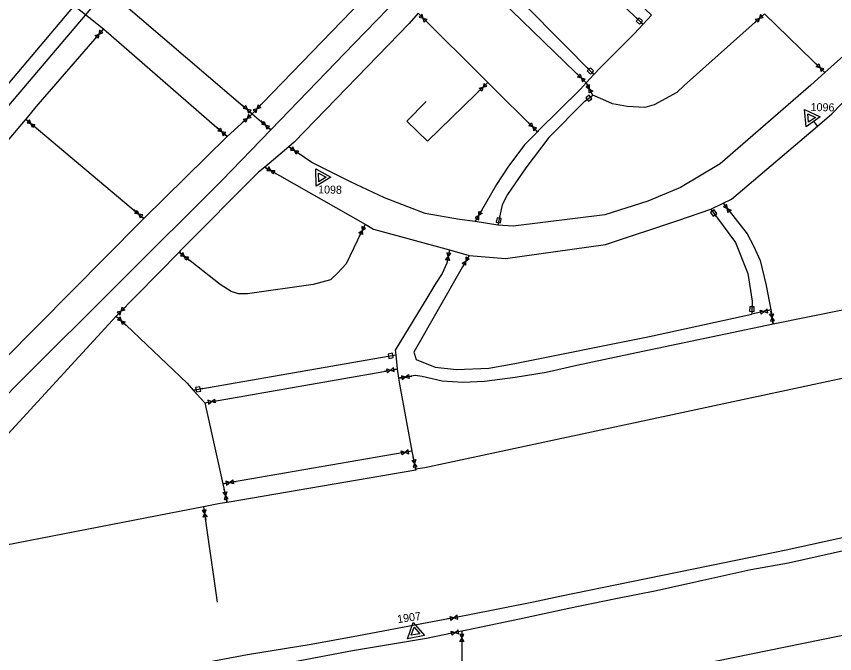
# Model space of a CAD drawing. Extents: x 349903 to 372392, y 368574 to 383062.
# Drawn here: x 364034 to 364545, y 373000 to 373398 of the extents above; entities that cross this region are included whole.
import ezdxf

# ---------------------------------------------------------------- set-up
doc = ezdxf.new("R2010")
doc.units = 0
for name, color, linetype in [('Niveau 1', 7, 'Continuous'), ('Niveau 10', 7, 'Continuous'), ('Niveau 2', 7, 'Continuous'), ('Niveau 3', 7, 'Continuous')]:
    doc.layers.add(name, color=color, linetype=linetype)

msp = doc.modelspace()

# ---------------------------------------------------------------- linework, layer by layer
at = {"layer": 'Niveau 1'}
for p, q in [((364289.667, 373395.829), (364291.017, 373394.491)), ((364496.537, 373395.811), (364495.128, 373394.535)), ((364088.295, 373390.713), (364086.932, 373389.11)), ((364084.096, 373385.772), (364082.865, 373384.323)), ((364534.581, 373367.935), (364533.221, 373369.264)), ((364539.218, 373363.403), (364537.713, 373364.874)), ((364385.435, 373361.514), (364384.074, 373362.841)), ((364390.076, 373356.986), (364388.57, 373358.456)), ((364328.606, 373357.213), (364327.099, 373355.744)), ((364390.076, 373356.986), (364391.049, 373355.12)), ((364323.964, 373352.686), (364322.602, 373351.359)), ((364393.076, 373351.238), (364393.956, 373349.553)), ((364176.457, 373341.864), (364175.022, 373343.111)), ((364185.872, 373342.257), (364187.197, 373343.619)), ((364181.35, 373337.609), (364179.762, 373338.99)), ((364181.35, 373337.609), (364182.818, 373339.117)), ((364039.803, 373334.226), (364041.414, 373332.872)), ((364176.528, 373333.273), (364175.115, 373332.002)), ((364181.35, 373337.609), (364179.785, 373336.202)), ((364188.062, 373331.899), (364186.626, 373333.144)), ((364044.766, 373330.054), (364046.222, 373328.83)), ((364160.727, 373327.798), (364159.3, 373329.055)), ((364192.961, 373327.651), (364191.371, 373329.03)), ((364355.018, 373331.016), (364353.668, 373332.354)), ((364359.624, 373326.452), (364358.13, 373327.933)), ((364165.592, 373323.512), (364164.013, 373324.903)), ((364204.197, 373317.088), (364205.928, 373315.892)), ((364209.532, 373313.403), (364211.096, 373312.322)), ((364189.144, 373304.348), (364190.972, 373303.305)), ((364194.777, 373301.136), (364196.428, 373300.195)), ((364475.621, 373281.87), (364476.907, 373280.205)), ((364108.711, 373276.334), (364107.258, 373277.56)), ((364323.967, 373275.88), (364324.928, 373277.521)), ((364479.585, 373276.739), (364480.748, 373275.234)), ((364113.667, 373272.153), (364112.059, 373273.51)), ((364320.689, 373270.286), (364321.753, 373272.101)), ((364251.918, 373268.632), (364250.995, 373266.741)), ((364249.076, 373262.804), (364248.242, 373261.096)), ((364135.58, 373251.205), (364137.229, 373249.898)), ((364304.607, 373252.578), (364304.194, 373250.515)), ((364140.662, 373247.179), (364142.153, 373245.998)), ((364303.335, 373246.22), (364302.962, 373244.356)), ((364316.87, 373249.202), (364315.806, 373247.386)), ((364313.592, 373243.607), (364312.631, 373241.967)), ((364100.909, 373215.889), (364102.24, 373217.246)), ((364096.37, 373211.258), (364097.844, 373212.761)), ((364096.37, 373211.258), (364097.902, 373209.815)), ((364499.034, 373213.671), (364497.178, 373213.261)), ((364505.366, 373215.068), (364503.311, 373214.615)), ((364505.789, 373212.546), (364505.502, 373214.426)), ((364101.091, 373206.813), (364102.475, 373205.51)), ((364506.764, 373206.136), (364506.448, 373208.216)), ((364265.558, 373177.067), (364263.686, 373176.736)), ((364271.943, 373178.196), (364269.871, 373177.83)), ((364272.778, 373172.441), (364274.856, 373172.775)), ((364279.18, 373173.471), (364281.057, 373173.773)), ((364151.663, 373157.064), (364153.735, 373157.43)), ((364158.048, 373158.192), (364159.92, 373158.523)), ((364274.71, 373125.754), (364272.837, 373125.424)), ((364281.095, 373126.881), (364279.023, 373126.516)), ((364282.231, 373121.369), (364281.834, 373123.229)), ((364283.584, 373115.028), (364283.145, 373117.086)), ((364169.412, 373107.669), (364171.286, 373107.994)), ((364163.024, 373106.559), (364165.097, 373106.919)), ((364164.187, 373101.213), (364163.783, 373103.07)), ((364165.567, 373094.877), (364165.12, 373096.933)), ((364150.943, 373092.135), (364151.269, 373090.056)), ((364151.95, 373085.73), (364152.245, 373083.851)), ((364305.231, 373022.411), (364303.363, 373022.059)), ((364311.603, 373023.61), (364309.535, 373023.221)), ((364305.929, 373013.091), (364304.066, 373012.711)), ((364312.283, 373014.384), (364310.221, 373013.965)), ((364312.283, 373014.384), (364312.282, 373012.28)), ((364312.282, 373007.9), (364312.281, 373005.998))]:
    msp.add_line(p, q, dxfattribs=at)
for points in [[(364290.557, 373396.733), (364288.786, 373394.935), (364287.46, 373399.804), (364285.677, 373398.018)], [(364497.391, 373394.874), (364495.692, 373396.739), (364500.625, 373397.801), (364498.937, 373399.677)], [(364085.065, 373384.954), (364083.137, 373386.582), (364087.89, 373388.278), (364085.972, 373389.918)], [(364533.697, 373367.025), (364535.455, 373368.835), (364536.817, 373363.977), (364538.586, 373365.776)], [(364384.552, 373360.603), (364386.308, 373362.415), (364387.674, 373357.557), (364389.442, 373359.358)], [(364324.852, 373351.781), (364323.085, 373353.582), (364327.975, 373354.826), (364326.219, 373356.639)], [(364394.199, 373351.829), (364391.966, 373350.654), (364392.181, 373355.695), (364389.94, 373354.535)], [(364184.96, 373343.138), (364186.773, 373341.384), (364181.918, 373340.012), (364183.722, 373338.246)], [(364175.628, 373340.904), (364177.278, 373342.813), (364178.919, 373338.042), (364180.581, 373339.941)], [(364045.579, 373331.027), (364043.962, 373329.09), (364042.24, 373333.834), (364040.61, 373331.907)], [(364177.38, 373332.333), (364175.687, 373334.204), (364180.623, 373335.249), (364178.941, 373337.131)], [(364187.235, 373330.938), (364188.882, 373332.85), (364190.53, 373328.081), (364192.189, 373329.982)], [(364159.892, 373326.844), (364161.554, 373328.743), (364163.164, 373323.961), (364164.839, 373325.849)], [(364354.129, 373330.112), (364355.899, 373331.91), (364357.227, 373327.042), (364359.009, 373328.829)], [(364210.249, 373314.449), (364208.822, 373312.368), (364206.661, 373316.927), (364205.22, 373314.856)], [(364195.401, 373302.24), (364194.158, 373300.044), (364191.612, 373304.4), (364190.355, 373302.212)], [(364107.897, 373275.363), (364109.518, 373277.296), (364111.23, 373272.55), (364112.864, 373274.473)], [(364322.871, 373276.518), (364325.052, 373275.249), (364320.666, 373272.755), (364322.839, 373271.472)], [(364480.586, 373277.517), (364478.594, 373275.969), (364477.92, 373280.969), (364475.918, 373279.433)], [(364250.217, 373262.252), (364247.946, 373263.351), (364252.129, 373266.172), (364249.865, 373267.285)], [(364141.447, 373248.175), (364139.886, 373246.192), (364138.028, 373250.884), (364136.454, 373248.911)], [(364304.579, 373245.975), (364302.103, 373246.463), (364305.435, 373250.252), (364302.962, 373250.755)], [(364314.689, 373242.97), (364312.507, 373244.239), (364316.893, 373246.733), (364314.72, 373248.016)], [(364100.001, 373216.773), (364101.808, 373215.012), (364096.947, 373213.659), (364098.744, 373211.886)], [(364499.311, 373212.434), (364498.76, 373214.896), (364503.571, 373213.373), (364503.035, 373215.839)], [(364101.957, 373207.739), (364100.233, 373205.897), (364098.782, 373210.729), (364097.046, 373208.897)], [(364504.536, 373212.351), (364507.029, 373212.739), (364505.192, 373208.039), (364507.688, 373208.411)], [(364265.783, 373175.819), (364265.336, 373178.302), (364270.078, 373176.578), (364269.646, 373179.065)], [(364278.974, 373174.722), (364279.383, 373172.232), (364274.668, 373174.029), (364275.061, 373171.537)], [(364157.823, 373159.44), (364158.27, 373156.957), (364153.528, 373158.681), (364153.959, 373156.195)], [(364274.934, 373124.506), (364274.488, 373126.99), (364279.229, 373125.264), (364278.799, 373127.751)], [(364280.992, 373121.101), (364283.458, 373121.635), (364281.902, 373116.835), (364284.372, 373117.354)], [(364169.191, 373108.917), (364169.631, 373106.433), (364164.894, 373108.171), (364165.318, 373105.683)], [(364162.949, 373100.939), (364165.413, 373101.483), (364163.877, 373096.677), (364166.345, 373097.206)], [(364153.202, 373085.931), (364150.71, 373085.531), (364152.525, 373090.239), (364150.03, 373089.855)], [(364305.469, 373021.166), (364304.995, 373023.644), (364309.755, 373021.973), (364309.297, 373024.453)], [(364306.186, 373011.849), (364305.675, 373014.32), (364310.46, 373012.719), (364309.965, 373015.193)], [(364313.549, 373007.904), (364311.027, 373007.897), (364313.55, 373012.265), (364311.027, 373012.274)]]:
    msp.add_lwpolyline(points, close=True, dxfattribs=at)
at = {"layer": 'Niveau 10'}
for p, q in [((364285.063, 373400.395), (364328.606, 373357.213)), ((364328.606, 373357.213), (364359.624, 373326.452)), ((364389.196, 373345.562), (364394.114, 373349.244)), ((364039.803, 373334.226), (364113.667, 373272.153)), ((364534.488, 373329.942), (364532.311, 373332.92)), ((364304.607, 373252.578), (364316.87, 373249.202)), ((364144.476, 373164.983), (364270.978, 373186.965)), ((364151.663, 373157.064), (364271.943, 373178.196)), ((364281.095, 373126.881), (364163.024, 373106.559)), ((364150.943, 373092.135), (364159.486, 373032.506)), ((364312.283, 373014.384), (364312.283, 372962.676))]:
    msp.add_line(p, q, dxfattribs=at)
for points in [[(366766.936, 376040.549), (366763.46, 376037.341), (366667.812, 375934.705), (366617.063, 375879.047), (366370.17, 375608.973), (366271.904, 375503.403), (366107.898, 375322.357), (365954.331, 375156.168), (365788.236, 374978.178), (365607.938, 374785.446), (365518.975, 374699.397), (365364.307, 374546.897), (365333.229, 374555.57), (364778.418, 374088.297), (364472.26, 373830.629), (364367.399, 373726.809), (364168.973, 373500.723), (364094.413, 373420.15), (363966.939, 373269.827), (363827.246, 373103.73), (363758.548, 373021.97), (363751.696, 373026.803)], [(364538.715, 373680.887), (364536.151, 373678.533), (364358.178, 373498.065), (364245.01, 373381.635), (364192.961, 373327.651)], [(364656.397, 373468.407), (364643.883, 373457.218), (364539.218, 373363.403)], [(364430.802, 373399.243), (364377.539, 373450.039), (364336.582, 373408.713), (364390.076, 373356.986)], [(364425.521, 373393.521), (364380.18, 373436.016), (364373.725, 373435.313), (364351.977, 373413.791), (364352.959, 373404.508), (364394.889, 373362.215)], [(364083.659, 373421.39), (364181.35, 373337.609)], [(364262.489, 373421.809), (364255.966, 373415.038), (364181.35, 373337.609)], [(364070.087, 373405.377), (364028.51, 373356.119), (364028.071, 373355.613)], [(364070.087, 373405.377), (364088.295, 373390.713)], [(364285.063, 373400.395), (364279.438, 373394.126), (364207.614, 373319.98), (364204.197, 373317.088)], [(364501.344, 373400.163), (364451.213, 373355.282), (364446.635, 373350.934), (364432.421, 373343.206), (364426.639, 373341.515), (364415.556, 373342.24), (364406.401, 373343.93), (364400.378, 373346.587), (364394.114, 373349.244)], [(364430.802, 373399.243), (364425.521, 373393.521)], [(364501.344, 373400.163), (364539.218, 373363.403)], [(364088.295, 373390.713), (364046.158, 373341.965), (364039.803, 373334.226)], [(364088.295, 373390.713), (364165.592, 373323.512)], [(364425.521, 373393.521), (364419.967, 373387.505), (364398.863, 373366.53), (364394.889, 373362.215)], [(364539.218, 373363.403), (364530.306, 373355.415), (364473.73, 373306.466), (364448.977, 373291.569), (364428.468, 373283.056), (364401.595, 373274.543), (364344.311, 373267.449), (364334.745, 373267.991)], [(364394.889, 373362.215), (364390.076, 373356.986)], [(364328.606, 373357.213), (364290.935, 373320.539), (364277.922, 373333.126), (364290.021, 373345.255)], [(364390.076, 373356.986), (364386.414, 373353.008), (364360.098, 373326.921), (364359.624, 373326.452)], [(364394.114, 373349.244), (364390.076, 373356.986)], [(364534.488, 373329.942), (364543.423, 373337.52), (364555, 373349.444)], [(364389.196, 373345.562), (364366.693, 373322.893), (364352.379, 373303.868), (364340.8, 373287.262), (364337.422, 373280.813), (364334.745, 373267.991)], [(364039.803, 373334.226), (364039.522, 373333.883), (363990.705, 373276.356), (363985.065, 373270.259)], [(364181.35, 373337.609), (364165.592, 373323.512)], [(364181.35, 373337.609), (364192.961, 373327.651)], [(364192.961, 373327.651), (364162.307, 373295.858), (364035.598, 373169.725), (363962.088, 373095.015), (363954.492, 373087.114)], [(364475.621, 373281.87), (364480.719, 373284.337), (364534.488, 373329.942)], [(364165.592, 373323.512), (364113.667, 373272.153)], [(364359.624, 373326.452), (364351.442, 373318.336), (364341.065, 373304.229), (364334.063, 373293.4), (364320.689, 373270.286)], [(364204.197, 373317.088), (364189.144, 373304.348)], [(364320.689, 373270.286), (364310.828, 373271.547), (364289.361, 373275.252), (364263.902, 373285.184), (364242.685, 373295.116), (364218.64, 373307.176), (364204.197, 373317.088)], [(364189.144, 373304.348), (364185.3, 373301.094), (364136.488, 373252.13), (364135.58, 373251.205)], [(364189.144, 373304.348), (364251.918, 373268.632)], [(364467.815, 373278.093), (364475.621, 373281.87)], [(364475.621, 373281.87), (364490.608, 373262.553), (364494.475, 373255.076), (364498.757, 373245.937), (364502.487, 373230.291), (364505.366, 373215.068)], [(364316.87, 373249.202), (364339.582, 373247.262), (364402.013, 373255.976), (364447.256, 373271.044), (364467.815, 373278.093)], [(364467.815, 373278.093), (364483.351, 373257.235), (364491.019, 373237.928), (364493.694, 373220.587), (364493.542, 373212.498)], [(364113.667, 373272.153), (364111.574, 373270.083), (363982.809, 373140.47)], [(364251.918, 373268.632), (364239.952, 373243.824), (364234.882, 373238.254), (364230.295, 373233.896), (364219.432, 373230.99), (364178.392, 373225.178), (364172.84, 373225.178), (364168.253, 373226.631), (364161.252, 373230.99), (364135.58, 373251.205)], [(364251.918, 373268.632), (364257.196, 373265.629), (364304.607, 373252.578)], [(364334.745, 373267.991), (364320.689, 373270.286)], [(364135.58, 373251.205), (364096.37, 373211.258)], [(364304.607, 373252.578), (364302.962, 373244.356), (364300.041, 373237.913), (364296.144, 373231.872), (364290.48, 373222.346), (364270.656, 373189.892), (364270.978, 373186.965)], [(364316.87, 373249.202), (364312.631, 373241.967), (364282.382, 373188.679), (364283.747, 373184.118), (364295.729, 373179.405), (364308.924, 373177.884), (364329.095, 373178.796), (364345.324, 373181.533), (364429.576, 373198.58), (364493.542, 373212.498)], [(364150.943, 373092.135), (364012.353, 373065.204), (364000.914, 373067.39), (363992.232, 373077.181), (363991.147, 373091.33), (364000.483, 373107.002), (364096.37, 373211.258)], [(364096.37, 373211.258), (364102.475, 373205.51), (364140.593, 373169.261), (364144.476, 373164.983)], [(364505.366, 373215.068), (364493.542, 373212.498)], [(364505.366, 373215.068), (364505.525, 373214.229), (364506.764, 373206.136)], [(364550.15, 373214.917), (364506.764, 373206.136)], [(364506.764, 373206.136), (364417.51, 373187.409), (364384.076, 373180.316), (364365.04, 373176.08), (364345.581, 373172.886), (364326.476, 373170.401), (364312.924, 373169.692), (364300.01, 373170.579), (364287.45, 373173.418), (364283.204, 373174.128), (364272.778, 373172.441)], [(364270.978, 373186.965), (364271.943, 373178.196)], [(364586.537, 373180.264), (364583.006, 373179.266), (364289.143, 373116.522), (364283.343, 373115.532)], [(364271.943, 373178.196), (364272.778, 373172.441)], [(364272.778, 373172.441), (364273.312, 373168.763), (364281.095, 373126.881)], [(364144.476, 373164.983), (364151.663, 373157.064)], [(364151.663, 373157.064), (364163.024, 373106.559)], [(364834.323, 373138.871), (364827.813, 373137.421), (364797.778, 373130.299), (364760.83, 373121.331), (364716.908, 373110.965), (364677.508, 373101.894), (364631.326, 373091.528), (364595.801, 373082.781), (364570.934, 373077.274), (364514.963, 373064.964), (364476.532, 373057.189), (364418.401, 373045.203), (364373.51, 373036.132), (364357.135, 373032.569), (364316.12, 373024.47), (364311.603, 373023.61)], [(364281.095, 373126.881), (364283.584, 373115.028)], [(364901.855, 372960.505), (364857.883, 373060.904), (364833.992, 373117.76), (364821.925, 373123.905), (364757.949, 373109.888), (364708.914, 373099.135), (364654.133, 373086.461), (364627.7, 373080.317), (364578.815, 373070.37), (364548.934, 373064.222), (364516.372, 373056.92), (364493.004, 373052.693), (364462.965, 373046.161), (364433.85, 373039.628), (364408.567, 373034.633), (364379.069, 373028.484), (364348.422, 373021.952), (364315.477, 373015.035), (364312.283, 373014.384)], [(364283.584, 373115.028), (364165.567, 373094.877)], [(364163.024, 373106.559), (364165.567, 373094.877)], [(364165.567, 373094.877), (364161.381, 373094.163), (364150.943, 373092.135)], [(364805.653, 372919.098), (364788.998, 372958.027), (364776.773, 372985.995), (364767.055, 373003.28), (364758.277, 373015.221), (364745.425, 373025.277), (364724.735, 373034.391), (364706.866, 373038.791), (364687.117, 373039.733), (364670.502, 373036.276), (364637.273, 373029.363), (364370.465, 372975.051), (364312.283, 372962.676)], [(364311.603, 373023.61), (364290.607, 373019.611), (364247.782, 373011.512), (364218.07, 373006.005), (364178.347, 372999.526), (364139.688, 372992.399), (364116.113, 372987.54), (364096.413, 372982.68), (364063.567, 372971.99), (364050.421, 372966.32), (363965.162, 372925.826), (363930.929, 372908.981), (363888.718, 372891.487), (363852.87, 372883.389), (363787.143, 372871.393)], [(364312.283, 373014.384), (364290.156, 373009.868), (364244.05, 373002.044), (364206.658, 372995.129), (364187.235, 372991.307), (364148.317, 372984.228), (364117.278, 372978.038), (364095.677, 372972.757), (364072.896, 372966.276), (364060.19, 372961.724), (364035.685, 372949.707), (364006.17, 372936.779), (363959.937, 372912.856), (363943.963, 372905.208), (363926.174, 372893.737), (363907.297, 372880.81), (363892.666, 372869.777), (363881.23, 372860.126), (363866.164, 372845.56), (363850.009, 372829.719), (363827.973, 372804.68)]]:
    msp.add_lwpolyline(points, dxfattribs=at)
at = {"layer": 'Niveau 2'}
for points in [[(364536.272, 373335.698), (364527.454, 373329.536), (364526.526, 373340.253)], [(364533.304, 373335.407), (364528.896, 373332.326), (364528.433, 373337.686)], [(364230.521, 373298.112), (364221.365, 373292.463), (364221.051, 373303.216)], [(364227.541, 373297.991), (364222.964, 373295.167), (364222.809, 373300.545)], [(364281.859, 373019.814), (364288.892, 373011.672), (364278.326, 373009.652)], [(364282.453, 373016.891), (364285.968, 373012.821), (364280.684, 373011.813)]]:
    msp.add_lwpolyline(points, close=True, dxfattribs=at)
at = {"layer": 'Niveau 3'}
for p, q in [((364421.028, 373397.712), (364422.216, 373396.604)), ((364424.247, 373394.709), (364425.521, 373393.521)), ((364390.562, 373366.577), (364391.706, 373365.424)), ((364393.662, 373363.452), (364394.889, 373362.215)), ((364392.72, 373348.199), (364394.114, 373349.244)), ((364389.196, 373345.562), (364390.496, 373346.535)), ((364468.86, 373276.699), (364467.815, 373278.093)), ((364336.012, 373274.003), (364335.678, 373272.413)), ((364471.501, 373273.177), (364470.526, 373274.477)), ((364335.104, 373269.696), (364334.745, 373267.991)), ((364493.649, 373218.641), (364493.621, 373217.017)), ((364493.572, 373214.24), (364493.542, 373212.498)), ((364264.922, 373185.932), (364266.523, 373186.205)), ((364269.261, 373186.672), (364270.978, 373186.965)), ((364146.193, 373165.278), (364144.476, 373164.983)), ((364150.531, 373166.022), (364148.931, 373165.747))]:
    msp.add_line(p, q, dxfattribs=at)
for points in [[(364423.287, 373393.68), (364425.161, 373395.688), (364423.146, 373397.567), (364421.273, 373395.559)], [(364392.663, 373362.46), (364394.613, 373364.394), (364392.673, 373366.35), (364390.723, 373364.416)], [(364393.563, 373347.073), (364391.917, 373349.272), (364389.713, 373347.621), (364391.359, 373345.423)], [(364469.986, 373277.544), (364467.789, 373275.896), (364469.441, 373273.693), (364471.638, 373275.34)], [(364333.727, 373269.986), (364336.414, 373269.419), (364336.983, 373272.114), (364334.295, 373272.681)], [(364492.165, 373214.264), (364494.911, 373214.216), (364494.959, 373216.97), (364492.213, 373217.018)], [(364269.498, 373185.285), (364269.036, 373187.992), (364266.321, 373187.529), (364266.783, 373184.822)], [(364145.955, 373166.665), (364146.419, 373163.958), (364149.134, 373164.423), (364148.669, 373167.13)]]:
    msp.add_lwpolyline(points, close=True, dxfattribs=at)

# ---------------------------------------------------------------- texts
at = {"layer": 'Niveau 2'}
for s, rotation, p in [('1096', 359, (364530.222, 373339.368)), ('1098', 359, (364222.462, 373287.89)), ('1907', 8.27232, (364272.3, 373019.394))]:
    msp.add_text(s, height=5, rotation=rotation, dxfattribs=at).set_placement(p)

doc.saveas('drawing.dxf')
